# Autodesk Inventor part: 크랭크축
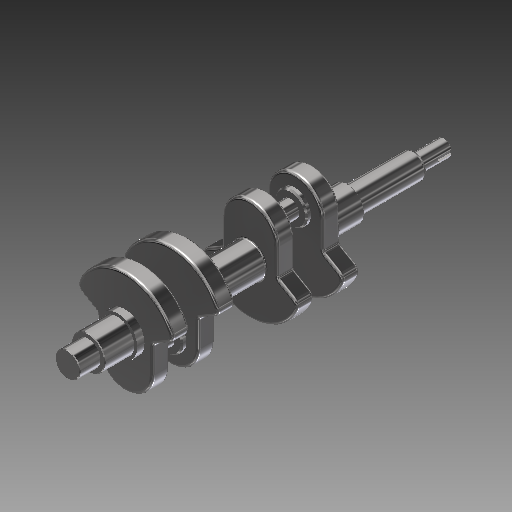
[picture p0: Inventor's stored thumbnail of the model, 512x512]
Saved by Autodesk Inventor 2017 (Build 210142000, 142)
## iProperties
Created: 2017-03
Part Number: 크랭크축
Material: 강철, 탄소
Document SubType Name: Modeling
Designer: mduedu
Density: 7.87 g/cm^3
Mass: 1576.89 g
Surface Area: 429.128 cm^2
Volume: 200.367 cm^3
Appearance: 반광택
Author: mduedu
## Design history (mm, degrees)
sketch "스케치1" dims "d5" = 50
  geometry: L1 (-19, 16.248)-(-19, -1.752); L2 (-19, -1.752)-(-33.503, -10.125); L3 (19, 16.248)-(19, -1.752); L4 (0, 16.248)-(0, -35); L5 (19, -1.752)-(33.503, -10.125); C1 r 8.5 at (0, 0); C2 r 13.5 at (0, 0); A1 r 35 centre (0, 0) between (-33.503, -10.125) and (0, -35); A2 r 35 centre (0, 0) between (0, -35) and (33.503, -10.125); A3 r 19 centre (0, 16.248) between (19, 16.248) and (0, 35.248); A4 r 19 centre (0, 16.248) between (0, 35.248) and (-19, 16.248); 3 further points
  constraints: 10 end point, 8 point on circle, 6 centre point, 5 coincident, 3 symmetric about line, 2 point on line, 1 parallel, 1 tangent, 1 vertical, 1 vertical alignment, 5 other
  dimensions: "d0" = 17 diameter of C1; "d1" = 27 diameter of C2; "d2" = 18 distance of L1.start L1.end; "d3" = 120 deg angle of L2 L1; "d4" = 35 radius of A1; "d6" = 19 radius of A4
extrude "돌출1" new body sketch "스케치1" distance "d7" = 12; taper "d8" = 0 deg
extrude "돌출2" join sketch "스케치1" distance "d9" = 5; taper "d10" = 0 deg
extrude "돌출3" join sketch "스케치1" distance "d11" = 90; taper "d12" = 0 deg
sketch "스케치2"
  geometry: C1 r 11 at (0, 16.248); C2 r 6 at (0, 16.248); A1 r 19 centre (0, 16.248) between (19, 16.248) and (-19, 16.248) reference; 1 further point
  constraints: 2 centre point, 2 coincident
  dimensions: "d13" = 22 diameter of C1; "d14" = 12 diameter of C2
extrude "돌출4" join sketch "스케치2" distance "d15" = 3; taper "d16" = 0 deg
extrude "돌출5" join sketch "스케치2" distance "d17" = 16; taper "d18" = 0 deg
fillet "모깎기1" dims "d19" = 3, "d20" = 5
fillet "모깎기2" dims "d21" = 2
sketch "스케치3"
  geometry: C1 r 11.5 at (0, 0); 1 further point
  constraints: 1 centre point, 1 coincident
  dimensions: "d22" = 23 diameter of C1
extrude "돌출6" join sketch "스케치3" distance "d23" = 19; taper "d24" = 0 deg
sketch "스케치4"
  geometry: C1 r 8.5 at (0, 0) reference; C2 r 5.5 at (0, 0); 1 further point
  constraints: 1 centre point
  dimensions: "d25" = 3 radial gap between concentric circles of C1 C2
extrude "돌출7" cut sketch "스케치4" distance "d26" = 20; taper "d27" = 0 deg
node "작업 평면1"
sketch "스케치5"
  geometry: L1 (-5.5, 0)-(5.5, 0) reference; L2 (-1.5, 0)-(1.5, 0); L3 (1.5, 0)-(1.5, 8.5); L4 (-1.5, 8.5)-(-1.5, 0); A1 r 1.5 centre (0, 8.5) between (1.5, 8.5) and (-1.5, 8.5); 1 further point
  constraints: 6 end point, 2 point on circle, 2 tangent, 1 centre point, 1 horizontal, 1 parallel, 1 perpendicular, 1 point on line, 1 vertical alignment
  dimensions: "d28" = 3 distance between parallel lines of L3 L4; "d30" = 10 dimension on A1 L1
extrude "돌출8" cut sketch "스케치5" distance "d31" = 1.8; taper "d32" = 0 deg
chamfer "모따기1" distance "d33" = 0.5; stored, may be unused: second distance "d34" = 2, angle "d35" = 45 deg
chamfer "모따기2" distance "d36" = 1; stored, may be unused: second distance "d37" = 2, angle "d38" = 45 deg
node "작업 평면2"
sketch "스케치6"
  geometry: C1 r 11.5 at (0, 0) reference; C2 r 11.5 at (0, 0) reference; 1 further point
extrude "돌출9" join sketch "스케치6" distance "d39" = 42; taper "d40" = 0 deg
sketch "스케치7" dims "d46" = 50
  geometry: L1 (-19, -16.248)-(-19, 1.752); L2 (19, -16.248)-(19, 1.752); L3 (-19, 1.752)-(-33.503, 10.125); L4 (19, 1.752)-(33.503, 10.125); L5 (0, -16.248)-(0, 35); C1 r 13.5 at (0, 0); C2 r 6 at (0, 0); A1 r 19 centre (0, -16.248) between (0, -35.248) and (19, -16.248); A2 r 19 centre (0, -16.248) between (-19, -16.248) and (0, -35.248); A3 r 35 centre (0, 0) between (0, 35) and (-33.503, 10.125); A4 r 35 centre (0, 0) between (33.503, 10.125) and (0, 35); 3 further points
  constraints: 10 end point, 8 point on circle, 6 centre point, 5 coincident, 3 symmetric about line, 2 point on line, 1 parallel, 1 tangent, 1 vertical, 5 other
  dimensions: "d41" = 12 diameter of C2; "d42" = 27 diameter of C1; "d43" = 18 distance of L2.start L2.end; "d44" = 120 deg angle of L4 L2; "d45" = 35 radius of A4; "d47" = 19 radius of A1
extrude "돌출10" join sketch "스케치7" distance "d48" = 12; taper "d49" = 0 deg
sketch "스케치8"
  geometry: C1 r 11 at (0, -16.248); C2 r 6 at (0, -16.248); A1 r 19 centre (0, -16.248) between (-19, -16.248) and (19, -16.248) reference; 1 further point
  constraints: 2 centre point, 2 coincident
  dimensions: "d50" = 22 diameter of C1; "d51" = 12 diameter of C2
extrude "돌출11" join sketch "스케치8" distance "d52" = 3; taper "d53" = 0 deg
extrude "돌출12" join sketch "스케치8" distance "d54" = 16; taper "d55" = 0 deg
fillet "모깎기3" dims "d56" = 3, "d57" = 5
fillet "모깎기4" dims "d58" = 2
chamfer "모따기3" distance "d59" = 1; stored, may be unused: second distance "d60" = 2, angle "d61" = 45 deg
node "작업 평면3"
fillet "모깎기5" dims "d62" = 1
sketch "스케치9"
  geometry: C1 r 13.5 at (0, 0) reference; 1 further point
extrude "돌출13" join sketch "스케치9" distance "d63" = 5; taper "d64" = 0 deg
sketch "스케치10"
  geometry: C1 r 8.5 at (0, 0) reference; C2 r 8.5 at (0, 0) reference; 1 further point
  dimensions: "d79" = 17 diameter of C1 (derived)
extrude "돌출14" join sketch "스케치10" distance "d65" = 34; taper "d66" = 0 deg
sketch "스케치11"
  geometry: C1 r 11.5 at (0, 0); 1 further point
  constraints: 1 centre point, 1 coincident
  dimensions: "d67" = 23 diameter of C1
extrude "돌출15" join sketch "스케치11" distance "d68" = 20; taper "d69" = 0 deg
chamfer "모따기4" distance "d70" = 0.5; stored, may be unused: second distance "d71" = 2, angle "d72" = 45 deg
sketch "스케치12"
  geometry: L1 (8.5, -70)-(-8.5, -70) reference; L2 (-8.5, -24)-(-8.5, -70) reference; L3 (-7.45, -70)-(-8.5, -68.181); L4 (5, -90)-(-5, -90) reference; L5 (0, -90)-(0, -70); 3 further points
  constraints: 4 end point, 2 midpoint, 2 point on line
  dimensions: "d80" = 14.9 diameter of L3.start L5; "d81" = 30 deg angle of L2 L3
revolve "회전1" sketch "스케치12" stored, may be unused: angle "d82" = 90 deg
fillet "모깎기7" dims "d83" = 2, "d84" = 1
node "솔리드1"
mirror "대칭1"
mirror "대칭2"
node "투영된 루프1"
node "투영된 루프2"
